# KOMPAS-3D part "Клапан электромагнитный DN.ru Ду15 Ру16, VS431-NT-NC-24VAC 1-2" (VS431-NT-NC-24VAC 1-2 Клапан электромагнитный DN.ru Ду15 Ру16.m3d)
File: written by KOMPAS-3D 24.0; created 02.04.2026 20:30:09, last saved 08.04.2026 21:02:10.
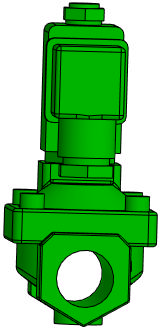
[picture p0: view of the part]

Document properties: Автор: artio; Полное имя файла: VS431-NT-NC-24VAC 1-2 Клапан электромагнитный DN.ru Ду15 Ру16.cdw

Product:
- Body: Тело 1  | qty 1
    Масса: 1.030062
- Part/product: Клапан электромагнитный DN.ru Ду15 Ру16  | designation VS431-NT-NC-24VAC 1-2
    Масса: 0.732
    Раздел спецификации: Прочие изделия
    Форматы листов документа: A3
    Примечание: D130-05631
    additional columns: ef56311e-7521-43dc-8291-0e6108b3d81d; VS400-ET-NC-220VAC 1-2; artio; c; Шероховатость не задана; Да

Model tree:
1. Операция без истории:1

Expressions: VS431-NT-NC-24VAC 1-2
